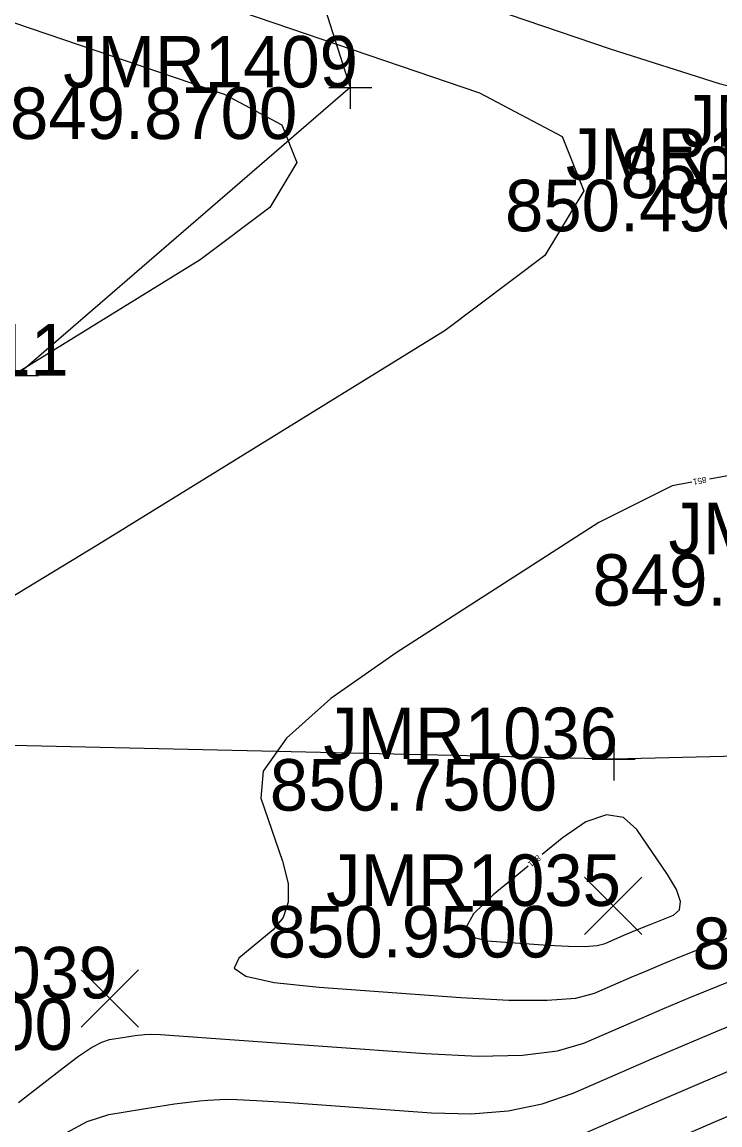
# Model space of a CAD drawing. Extents: x 1654928 to 1810050, y 486881 to 626330.
# Drawn here: x 1801379.97 to 1801396.23, y 489814.52 to 489840.21 of the extents above; entities that cross this region are included whole.
import ezdxf

# ---------------------------------------------------------------- set-up
doc = ezdxf.new("R2010")
doc.units = 0
for name, color, linetype in [('DT_X_Contour_Major', 7, 'Continuous'), ('DT_X_Contour_Minor', 7, 'Continuous'), ('RD_X_Fence', 7, 'Continuous'), ('SV_X_Occupation_Line', 7, 'Continuous'), ('SV_X_Random_Point', 7, 'Continuous'), ('SV_X_Shot_Marker', 7, 'Continuous'), ('SV_X_Text_Elevation', 7, 'Continuous'), ('SV_X_Text_Name', 7, 'Continuous')]:
    doc.layers.add(name, color=color, linetype=linetype)

msp = doc.modelspace()

# ---------------------------------------------------------------- linework, layer by layer
at = {"layer": 'DT_X_Contour_Major'}
msp.add_lwpolyline([(1801392.561, 489814.105), (1801394.885, 489815.115), (1801395.757, 489815.49), (1801396.632, 489815.859)], dxfattribs=at)
at = {"layer": 'DT_X_Contour_Minor'}
for points in [[(1801379.576, 489847.059), (1801380.072, 489844.264), (1801381.422, 489842.228), (1801383.624, 489840.951), (1801390.633, 489838.561), (1801392.555, 489837.542), (1801393.062, 489836.281), (1801392.154, 489834.777), (1801389.832, 489833.029), (1801381.754, 489828.045), (1801379.039, 489826.396)], [(1801386.203, 489842.133), (1801393.676, 489839.584), (1801396.214, 489838.78), (1801398.222, 489838.279), (1801399.7, 489838.08), (1801400.648, 489838.185), (1801402.471, 489838.868), (1801403.08, 489839.07), (1801403.54, 489839.161), (1801403.85, 489839.143), (1801404.012, 489839.016), (1801404.243, 489838.529), (1801404.287, 489838.342), (1801404.245, 489838.145), (1801404.118, 489837.939), (1801403.905, 489837.723), (1801403.224, 489837.134), (1801403.1, 489836.715), (1801403.237, 489835.899), (1801403.637, 489834.687), (1801404.299, 489833.079), (1801404.416, 489832.813)], [(1801379.799, 489840.194), (1801384.685, 489838.528), (1801386.024, 489837.818), (1801386.377, 489836.939), (1801385.745, 489835.891), (1801384.126, 489834.673), (1801378.496, 489831.199)], [(1801394.166, 489817.962), (1801394.506, 489818.108), (1801394.884, 489818.266), (1801395.3, 489818.436), (1801397.013, 489819.124), (1801397.393, 489819.338), (1801397.589, 489819.601), (1801397.599, 489819.915), (1801397.425, 489820.278), (1801396.714, 489821.313), (1801396.658, 489821.676), (1801397.022, 489821.988), (1801397.807, 489822.25), (1801399.012, 489822.461), (1801405.615, 489823.327), (1801399.547, 489828.578), (1801398.188, 489829.421), (1801396.712, 489829.697), (1801395.991, 489829.566)], [(1801395.578, 489829.491), (1801395.119, 489829.408), (1801393.409, 489828.552), (1801388.692, 489825.517), (1801387.168, 489824.452), (1801386.134, 489823.533), (1801385.59, 489822.761), (1801385.535, 489822.136), (1801386.042, 489820.664), (1801386.171, 489820.15), (1801386.177, 489819.713), (1801386.06, 489819.351), (1801385.821, 489819.065), (1801385.02, 489818.405), (1801384.912, 489818.177), (1801385.188, 489817.989), (1801385.849, 489817.84), (1801386.894, 489817.73), (1801390.193, 489817.491), (1801391.316, 489817.43), (1801392.21, 489817.426), (1801392.874, 489817.479), (1801393.31, 489817.59), (1801394.166, 489817.962)], [(1801393.926, 489818.911), (1801394.234, 489819.041), (1801394.607, 489819.193), (1801395.147, 489819.409), (1801395.29, 489819.529), (1801395.316, 489819.727), (1801395.223, 489820.003), (1801395.012, 489820.357), (1801394.293, 489821.404), (1801393.983, 489821.685), (1801393.589, 489821.745), (1801393.112, 489821.583), (1801392.553, 489821.199), (1801392.09, 489820.818)], [(1801391.766, 489820.551), (1801390.951, 489819.879), (1801390.491, 489819.441), (1801390.315, 489819.117), (1801390.421, 489818.908), (1801390.81, 489818.812), (1801392.224, 489818.709), (1801392.705, 489818.683), (1801393.088, 489818.681), (1801393.373, 489818.704), (1801393.56, 489818.752), (1801393.926, 489818.911)], [(1801379.892, 489815.046), (1801380.932, 489815.856), (1801381.291, 489816.124), (1801381.592, 489816.323), (1801381.832, 489816.452), (1801382.013, 489816.511), (1801382.416, 489816.576), (1801382.555, 489816.597), (1801382.67, 489816.613), (1801382.761, 489816.624), (1801382.829, 489816.629), (1801382.978, 489816.636), (1801383.195, 489816.626), (1801383.734, 489816.591), (1801384.595, 489816.531), (1801389.363, 489816.185), (1801390.602, 489816.127), (1801391.631, 489816.148), (1801392.451, 489816.249), (1801393.06, 489816.428), (1801394.406, 489817.013), (1801394.94, 489817.242), (1801395.534, 489817.49), (1801396.187, 489817.758), (1801396.9, 489818.046)], [(1801380.811, 489814.238), (1801381.489, 489814.602), (1801381.998, 489814.768), (1801383.133, 489814.95), (1801383.525, 489815.011), (1801383.85, 489815.056), (1801384.108, 489815.086), (1801384.299, 489815.101), (1801384.719, 489815.12), (1801384.977, 489815.117), (1801385.435, 489815.095), (1801386.094, 489815.054), (1801386.954, 489814.994), (1801389.514, 489814.808), (1801390.44, 489814.784), (1801391.298, 489814.853), (1801392.088, 489815.014), (1801392.81, 489815.266), (1801394.645, 489816.064), (1801395.374, 489816.376), (1801396.183, 489816.715), (1801397.074, 489817.08)], [(1801395.124, 489814.166), (1801396.132, 489814.601), (1801397.046, 489814.989)]]:
    msp.add_lwpolyline(points, dxfattribs=at)
at = {"layer": 'RD_X_Fence'}
msp.add_lwpolyline([(1801327.157, 489980.825), (1801341.337, 489952.815), (1801353.978, 489927.719), (1801368.649, 489898.399), (1801382.749, 489869.731), (1801399.284, 489836.538), (1801405.615, 489823.327), (1801393.757, 489823.044), (1801375.98, 489823.449), (1801361.092, 489823.97), (1801335.059, 489824.221), (1801306.244, 489824.992)], dxfattribs=at)
at = {"layer": 'SV_X_Occupation_Line'}
msp.add_lwpolyline([(1801323.637, 489975.339), (1801342.746, 489938.404), (1801356.309, 489913.548), (1801376.911, 489872.203), (1801387.619, 489838.687), (1801379.855, 489831.976), (1801347.713, 489831.536), (1801304.639, 489830.454)], dxfattribs=at)
at = {"layer": 'SV_X_Random_Point'}
for p, q in [((1801393.08, 489818.956), (1801394.413, 489820.291)), ((1801393.08, 489820.291), (1801394.413, 489818.956)), ((1801381.354, 489816.802), (1801382.688, 489818.137)), ((1801381.354, 489818.137), (1801382.688, 489816.802))]:
    msp.add_line(p, q, dxfattribs=at)
at = {"layer": 'SV_X_Shot_Marker'}
for p, q in [((1801387.619, 489839.187), (1801387.619, 489838.187)), ((1801387.119, 489838.687), (1801388.119, 489838.687)), ((1801387.619, 489838.687), (1801387.619, 489838.687)), ((1801379.355, 489831.976), (1801380.355, 489831.976)), ((1801393.757, 489823.544), (1801393.757, 489822.544)), ((1801393.257, 489823.044), (1801394.257, 489823.044)), ((1801393.757, 489823.044), (1801393.757, 489823.044))]:
    msp.add_line(p, q, dxfattribs=at)

# ---------------------------------------------------------------- texts
at = {"layer": 'DT_X_Contour_Minor'}
for rotation, p in [(190.2978, (1801395.903, 489829.621)), (219.4884, (1801391.986, 489820.823))]:
    msp.add_text('851', height=0.14, rotation=rotation, dxfattribs=at).set_placement(p)
at = {"layer": 'SV_X_Text_Elevation'}
for s, p in [('849.8700', (1801379.692, 489837.487)), ('850.4300', (1801393.916, 489836.109)), ('850.4900', (1801391.225, 489835.338)), ('849.5900', (1801393.265, 489826.616)), ('850.7500', (1801385.745, 489821.844)), ('850.9500', (1801385.697, 489818.423)), ('850.1700', (1801395.593, 489818.153)), ('850.5100', (1801374.463, 489816.27))]:
    msp.add_text(s, height=1.2, dxfattribs=at).set_placement(p)
at = {"layer": 'SV_X_Text_Name'}
for s, p in [('JMR1409', (1801380.931, 489838.687)), ('JMR1025', (1801395.325, 489837.309)), ('JMR1024', (1801392.643, 489836.538)), ('JMR1411', (1801374.196, 489831.976)), ('JMR1410', (1801395.033, 489827.816)), ('JMR1036', (1801386.992, 489823.044)), ('JMR1035', (1801387.058, 489819.623)), ('JMR1039', (1801375.323, 489817.47))]:
    msp.add_text(s, height=1.2, dxfattribs=at).set_placement(p)

doc.saveas('drawing.dxf')
